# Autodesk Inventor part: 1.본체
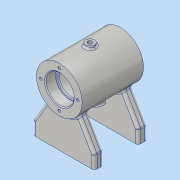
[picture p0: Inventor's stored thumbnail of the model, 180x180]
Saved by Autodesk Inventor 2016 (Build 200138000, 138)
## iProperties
Created: 2018-05
Part Number: 1.본체
Material: 알루미늄 6061
Document SubType Name: Modeling
Designer: 605-04
Density: 2.7 g/cm^3
Appearance: 알루미늄 - 평지
Mass: 317.681 g
Surface Area: 375.844 cm^2
Volume: 117.66 cm^3
Author: 605-04
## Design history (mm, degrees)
sketch "스케치1"
  geometry: C1 r 26 at (0, 0); 1 further point
  constraints: 1 centre point, 1 coincident
  dimensions: "d0" = 52 diameter of C1
extrude "돌출1" new body sketch "스케치1" stored distance "d1" = 70; taper "d2" = 0 deg
sketch "스케치2"
  geometry: L1 (26, 35)-(-26, 35) reference; L2 (-26, -35)-(26, -35) reference; L3 (0, 35)-(0, -35); L4 (16, 35)-(16, 23); L5 (16, 23)-(14, 23); L6 (14, 23)-(14, 21); L7 (14, 21)-(21, 21); L8 (21, 21)-(21, -21); L9 (21, -21)-(14, -21); L10 (14, -21)-(14, -23); L11 (14, -23)-(16, -23); L12 (16, -23)-(16, -35); L13 (0, 35)-(16, 35); L14 (0, -35)-(16, -35); 1 further point
  constraints: 24 end point, 6 perpendicular, 6 point on line, 2 midpoint, 1 horizontal, 1 parallel, 1 vertical
  dimensions: "d3" = 28 diameter of L6 L3; "d4" = 32 diameter of L4 L3; "d5" = 42 diameter of L8 L3; "d6" = 12 distance of L4.start L4.end; "d7" = 2 distance of L5.end L6.end; "d8" = 12 distance of L11.end L12.end; "d9" = 2 distance of L9.end L10.end
revolve "회전1" sketch "스케치2" stored, may be unused: angle "d10" = 90 deg
node "작업 평면1"
sketch "스케치3"
  geometry: L1 (-17.325, -19.386)-(-35, -50); L2 (-35, -50)-(-35, -65); L3 (-35, -65)-(35, -65); L4 (35, -65)-(35, -50); L5 (35, -50)-(17.325, -19.386); A1 r 26 centre (0, 0) between (-17.325, -19.386) and (17.325, -19.386) reference; 1 further point
  constraints: 10 end point, 2 equal length, 2 perpendicular, 2 point on circle, 1 vertical
  dimensions: "d13" = 30 deg angle of L4 L5; "d14" = 30 deg angle of L2 L1 (= d13); "d15" = 70 distance of L2.end L3.end; "d16" = 65 distance from line of L3 point (0, 0); "d104" = 15 distance of L1.end L2.end
extrude "돌출2" join sketch "스케치3" distance "d17" = 10; taper "d18" = 0 deg
node "작업 평면2"
sketch "스케치4"
  geometry: L1 (-17.325, -19.386)-(-35, -50); L2 (-35, -50)-(-35, -65); L3 (-35, -65)-(35, -65); L4 (35, -65)-(35, -50); L5 (35, -50)-(17.325, -19.386); A1 r 26 centre (0, 0) between (-17.325, -19.386) and (17.325, -19.386) reference; 1 further point
  constraints: 10 end point, 2 equal length, 2 perpendicular, 2 point on circle, 1 vertical
  dimensions: "d20" = 15 distance of L3.end L4.end; "d21" = 70 distance of L2.end L3.end; "d22" = 30 deg angle of L4 L5; "d23" = 30 deg angle of L1 L2 (= d22); "d24" = 65 distance from line of L3 point (0, 0)
extrude "돌출3" join sketch "스케치4" distance "d25" = 10; taper "d26" = 0 deg
node "작업 평면3"
sketch "스케치5"
  geometry: C1 r 5 at (0, 0); 1 further point
  constraints: 1 centre point, 1 coincident
  dimensions: "d28" = 10 diameter of C1
extrude "돌출4" join sketch "스케치5" stored distance "d29" = 10; taper "d30" = 0 deg
sketch "스케치6"
  geometry: L1 (0, 0)-(0, -26); L2 (0, 0)-(9.919, -27.251); 1 further point
  constraints: 4 end point, 1 vertical, 1 vertical alignment, 1 other
  dimensions: "d31" = 20 deg angle of L2 L1; "d32" = 29 distance of L1.start L2.end
node "작업 평면4"
sketch "스케치7"
  geometry: C1 r 6 at (0, 0); 1 further point
  constraints: 1 centre point, 1 coincident
  dimensions: "d33" = 12 diameter of C1
extrude "돌출5" join sketch "스케치7" stored distance "d34" = 10; taper "d35" = 0 deg
sketch "스케치8" dims "d36" = 42
  geometry: 3 further points
  constraints: 2 vertical alignment, 1 coincident, 2 other
hole "구멍1" sketch "스케치8" at (0, 21) diameter "d37" = 3.242; stored, may be unused: countersink angle "d41" = 90 deg, drill point angle "d43" = 118 deg; dims "d38" = 8, "d39" = 4, "d40" = 2, "d42" = 10
sketch "스케치9"
  geometry: C1 r 21 at (0, 0); C2 r 1.621 at (0, 21) reference; 2 further points
  constraints: 2 coincident, 1 centre point
  dimensions: "d47" = 42 diameter of C1
hole "구멍2" sketch "스케치9" at (0, 21) diameter "d48" = 3.242; stored, may be unused: countersink angle "d52" = 90 deg, drill point angle "d54" = 118 deg; dims "d49" = 8, "d50" = 4, "d51" = 2, "d53" = 10
hole "구멍3" diameter "d60" = 5.188; stored, may be unused: countersink angle "d64" = 90 deg, drill point angle "d66" = 118 deg; dims "d58" = 10, "d59" = 10, "d61" = 12, "d62" = 4, "d63" = 2, "d65" = 16
hole "구멍4" diameter "d69" = 5.188; stored, may be unused: countersink angle "d73" = 90 deg, drill point angle "d75" = 118 deg; dims "d67" = 10, "d68" = 10, "d70" = 12, "d71" = 4, "d72" = 2, "d74" = 16
sketch "스케치10"
  geometry: L1 (0, 50)-(70, 50) reference; L2 (0, 0)-(70, 0) reference; 5 further points
  dimensions: "d76" = 20 horizontal distance of point (55, 45) point (35, 20); "d77" = 5 distance from line of point (55, 45) L1; "d78" = 20 horizontal distance of point (55, -5) point (35, 20) (= d76); "d79" = 20 horizontal distance of point (15, -5) point (35, 20) (= d76); "d80" = 20 horizontal distance of point (15, 45) point (35, 20) (= d76); "d81" = 5 distance from line of point (55, -5) L2 (= d77); "d82" = 5 distance from line of point (15, 45) L1 (= d77); "d83" = 5 distance from line of point (15, -5) L2 (= d77)
hole "구멍5" sketch "스케치10" at (55, 45), (15, 45), (55, -5), (15, -5) diameter "d84" = 4.134; stored, may be unused: countersink angle "d88" = 90 deg, drill point angle "d90" = 118 deg; dims "d85" = 8, "d86" = 4, "d87" = 2, "d89" = 10
chamfer "모따기1" distance "d91" = 1; stored, may be unused: second distance "d92" = 2, angle "d93" = 45 deg
fillet "모깎기1" dims "d94" = 0.3
fillet "모깎기2" dims "d95" = 3
fillet "모깎기3" dims "d96" = 2
fillet "모깎기4" dims "d97" = 3
fillet "모깎기5" dims "d98" = 3
fillet "모깎기6" dims "d99" = 3
node "작업 평면5"
sketch "스케치11"
  geometry: L1 (-26, -35)-(26, -35) reference; 2 further points
  constraints: 1 other
  dimensions: "d100" = 35 distance from line of point (0, 0) L1; "d101" = 26 horizontal distance of L1.start point (0, 0)
feature "엠보싱1" sketch "스케치11" dims "d102" = 0.5, "d103" = 0
node "솔리드1"
pattern_circular "원형 패턴1" dims angle "d45" = 360 deg
pattern_circular "원형 패턴2" dims angle "d56" = 360 deg
other parameters: "d27" = 29
